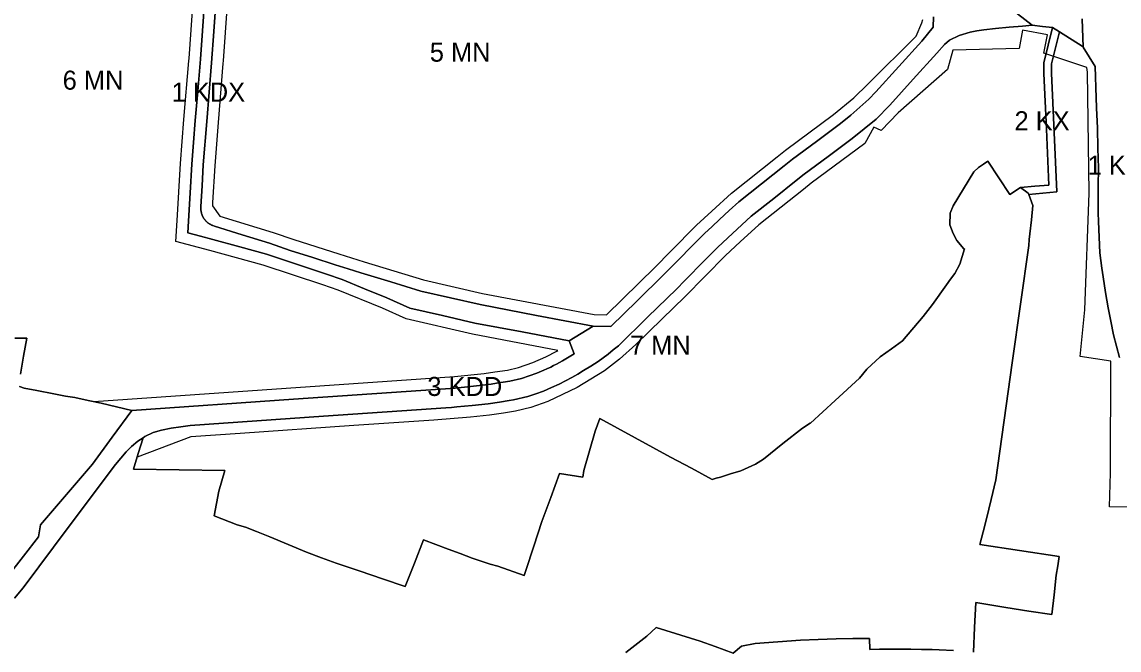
# Model space of a CAD drawing. Extents: x -294445 to -292055, y 21869 to 23693.
# Drawn here: x -294152 to -293575, y 22472 to 22801 of the extents above; entities that cross this region are included whole.
import ezdxf

# ---------------------------------------------------------------- set-up
doc = ezdxf.new("R2010")
doc.units = 0
for name, color, linetype in [('linie_rozgraniczajace', 7, 'Continuous'), ('linie_zabudowy_nieprzekraczalne', 7, 'Continuous'), ('oznaczenia_przeznaczen', 7, 'Continuous')]:
    doc.layers.add(name, color=color, linetype=linetype)

msp = doc.modelspace()

# ---------------------------------------------------------------- linework, layer by layer
at = {"layer": 'linie_rozgraniczajace'}
for points in [[(-294055.939, 22811.926), (-294056.993, 22796.91), (-294058.047, 22781.895), (-294059.436, 22765.133), (-294060.723, 22749.688), (-294061.62, 22738.233), (-294062.516, 22726.779), (-294063.392, 22711.785), (-294064.269, 22696.791), (-294064.663, 22690.759), (-294058.067, 22689.014), (-294051.47, 22687.27), (-294037.37, 22683.355), (-294023.27, 22679.44), (-294007.52, 22674.26), (-293991.77, 22669.08), (-293983.521, 22666.139), (-293971.745, 22661.379), (-293959.97, 22656.62), (-293947.94, 22651.2)], [(-294064.663, 22690.759), (-294064.269, 22696.791), (-294063.392, 22711.785), (-294062.516, 22726.779), (-294061.62, 22738.233), (-294060.723, 22749.688), (-294059.436, 22765.133), (-294058.047, 22781.895), (-294056.993, 22796.91), (-294055.939, 22811.926)], [(-294054.871, 22696.625), (-294055.01, 22696.764), (-294055.147, 22696.905), (-294055.281, 22697.05), (-294055.412, 22697.197), (-294055.54, 22697.346), (-294055.665, 22697.498), (-294055.787, 22697.653), (-294055.905, 22697.81), (-294056.021, 22697.97), (-294056.133, 22698.132), (-294056.241, 22698.296), (-294056.347, 22698.462), (-294056.449, 22698.63), (-294056.547, 22698.801), (-294056.643, 22698.973), (-294056.734, 22699.147), (-294056.822, 22699.323), (-294056.907, 22699.501), (-294056.987, 22699.681), (-294057.065, 22699.862), (-294057.138, 22700.044), (-294057.208, 22700.229), (-294057.274, 22700.414), (-294057.336, 22700.601), (-294057.394, 22700.789), (-294057.449, 22700.978), (-294057.499, 22701.168), (-294057.546, 22701.359), (-294057.589, 22701.551), (-294057.628, 22701.744), (-294057.663, 22701.938), (-294057.694, 22702.132), (-294057.721, 22702.327), (-294057.745, 22702.523), (-294057.764, 22702.719), (-294057.779, 22702.915), (-294057.79, 22703.112), (-294057.798, 22703.308), (-294057.801, 22703.505), (-294057.8, 22703.702), (-294057.795, 22703.899), (-294057.787, 22704.095), (-294057.774, 22704.292), (-294057.757, 22704.488), (-294057.144, 22715.429), (-294056.53, 22726.37), (-294054.742, 22749.204), (-294053.455, 22764.651), (-294052.168, 22780.098), (-294051.011, 22796.447), (-294049.96, 22811.42)], [(-294049.96, 22811.42), (-294051.011, 22796.447)], [(-293632.243, 22808.79), (-293620.646, 22799.786), (-293625.664, 22799.312), (-293632.795, 22798.707), (-293639.941, 22798.101), (-293646.104, 22797.435), (-293649.699, 22796.816), (-293653.294, 22796.197), (-293659.122, 22794.43), (-293664.139, 22791.899), (-293666.793, 22789.583), (-293670.859, 22785.131), (-293683.199, 22771.475), (-293695.538, 22757.82), (-293702.68, 22750.51), (-293708.999, 22745.357), (-293715.319, 22740.204), (-293727.944, 22730.846), (-293740.569, 22721.487), (-293744.698, 22718.136), (-293756.539, 22708.788), (-293768.379, 22699.441), (-293773.297, 22694.898), (-293778.214, 22690.355), (-293786.036, 22683.22), (-293792.729, 22676.434), (-293803.497, 22665.517), (-293807.573, 22661.384)], [(-293594.377, 22803.197), (-293593.872, 22788.256), (-293594.388, 22788.781), (-293606.347, 22796.324), (-293609.914, 22798.578), (-293615.28, 22799.182), (-293620.646, 22799.786), (-293632.243, 22808.79)], [(-294159.072, 22510.604), (-294151.168, 22520.795), (-294143.263, 22530.986), (-294142.717, 22534.173), (-294142.17, 22537.36), (-294128.512, 22553.28), (-294114.854, 22569.199), (-294104.502, 22583.335), (-294094.15, 22597.47), (-294009.075, 22603.335), (-293924, 22609.2), (-293916.062, 22610.027), (-293908.124, 22610.853), (-293905.203, 22611.265), (-293902.282, 22611.677), (-293895.42, 22612.762), (-293889.148, 22614.248), (-293885.152, 22615.6), (-293881.157, 22616.953), (-293877.46, 22618.558), (-293875.901, 22619.235), (-293873.763, 22620.163), (-293872.289, 22620.948), (-293870.724, 22621.781), (-293867.684, 22623.4), (-293861.421, 22627.116), (-293864.117, 22633.958), (-293851.523, 22641.744), (-293842.173, 22641.565), (-293828.4, 22655.019), (-293814.627, 22668.473), (-293810.584, 22672.572), (-293806.541, 22676.671), (-293799.756, 22683.551), (-293792.97, 22690.43), (-293788.985, 22694.065), (-293785, 22697.7), (-293779.94, 22702.375), (-293774.88, 22707.05), (-293762.94, 22716.475), (-293751, 22725.9), (-293746.7, 22729.39), (-293734.08, 22738.745), (-293721.459, 22748.1), (-293715.926, 22752.612), (-293706.589, 22760.92), (-293702.785, 22764.716), (-293690.713, 22778.075), (-293678.641, 22791.434), (-293672.799, 22798.844), (-293672.605, 22804.206)], [(-293672.605, 22804.206), (-293672.799, 22798.844), (-293678.641, 22791.434), (-293690.713, 22778.075), (-293702.785, 22764.716), (-293706.589, 22760.92), (-293715.926, 22752.612), (-293721.459, 22748.1), (-293734.08, 22738.745), (-293746.7, 22729.39), (-293751, 22725.9), (-293762.94, 22716.475), (-293774.88, 22707.05), (-293779.94, 22702.375), (-293785, 22697.7), (-293788.985, 22694.065), (-293792.97, 22690.43), (-293799.756, 22683.551), (-293806.541, 22676.671), (-293810.584, 22672.572), (-293814.627, 22668.473), (-293828.4, 22655.019), (-293842.173, 22641.565), (-293851.523, 22641.744), (-293881.264, 22647.374), (-293911.005, 22653.003), (-293926.61, 22656.574), (-293942.214, 22660.145), (-293957.921, 22664.911), (-293973.627, 22669.677), (-293980.377, 22671.79), (-293987.128, 22673.902), (-293998.959, 22677.711), (-294010.79, 22681.52), (-294021.665, 22685.221), (-294036.129, 22689.701), (-294050.592, 22694.182), (-294051.592, 22694.525), (-294051.759, 22694.591), (-294051.941, 22694.667), (-294052.121, 22694.747), (-294052.299, 22694.83), (-294052.476, 22694.917), (-294052.651, 22695.008), (-294052.824, 22695.102), (-294052.995, 22695.199), (-294053.164, 22695.3), (-294053.331, 22695.404), (-294053.496, 22695.512), (-294053.658, 22695.623), (-294053.818, 22695.737), (-294053.976, 22695.855), (-294054.132, 22695.976), (-294054.285, 22696.099), (-294054.435, 22696.226), (-294054.583, 22696.356), (-294054.728, 22696.489), (-294054.871, 22696.625)], [(-293574.744, 22625.222), (-293577.87, 22637.216), (-293579.304, 22644.235), (-293580.738, 22651.254), (-293582.053, 22659.409), (-293583.368, 22667.564), (-293584.1, 22672.161), (-293584.572, 22676.205), (-293585.045, 22680.249), (-293585.422, 22688.433), (-293585.799, 22696.617), (-293585.885, 22701.145), (-293585.97, 22705.674), (-293585.87, 22715.192), (-293585.77, 22724.711), (-293586.07, 22735.224), (-293586.369, 22745.737), (-293586.761, 22756.424), (-293587.153, 22767.111), (-293587.332, 22772.613), (-293587.511, 22778.115), (-293593.872, 22788.256), (-293594.377, 22803.197)], [(-294093.3, 22566.59), (-294090.744, 22574.851), (-294088.188, 22583.112), (-294087.198, 22583.768), (-294082.911, 22585.833), (-294078.507, 22587.079), (-294073.362, 22588.17), (-294068.385, 22588.878), (-294063.428, 22589.564), (-293993.283, 22594.4), (-293928.929, 22598.836), (-293925.936, 22599.043), (-293923.138, 22599.236), (-293915.113, 22600.071), (-293906.727, 22600.951), (-293900.803, 22601.787), (-293895.655, 22602.601), (-293893.484, 22602.944), (-293885.941, 22604.776), (-293881.748, 22606.195), (-293877.556, 22607.615), (-293873.485, 22609.382), (-293869.415, 22611.149), (-293866.1, 22612.914), (-293862.784, 22614.679), (-293859.659, 22616.53), (-293856.533, 22618.381), (-293852.72, 22620.741), (-293848.906, 22623.101), (-293846.275, 22625.045), (-293843.644, 22626.988), (-293840.949, 22629.202), (-293838.255, 22631.416), (-293822.914, 22646.4), (-293807.573, 22661.384), (-293803.497, 22665.517), (-293792.729, 22676.434), (-293786.036, 22683.22), (-293778.214, 22690.355), (-293773.297, 22694.898), (-293768.379, 22699.441), (-293756.539, 22708.788), (-293744.698, 22718.136), (-293740.569, 22721.487), (-293727.944, 22730.846), (-293715.319, 22740.204), (-293708.999, 22745.357), (-293702.68, 22750.51), (-293695.538, 22757.82), (-293683.199, 22771.475), (-293670.859, 22785.131), (-293666.793, 22789.583), (-293664.139, 22791.899), (-293659.122, 22794.43), (-293653.294, 22796.197), (-293649.699, 22796.816), (-293646.104, 22797.435), (-293639.941, 22798.101), (-293632.795, 22798.707), (-293625.664, 22799.312), (-293620.646, 22799.786), (-293615.28, 22799.182), (-293609.914, 22798.578), (-293612.182, 22789.317), (-293614.45, 22780.055), (-293614.446, 22774.491), (-293613.144, 22745.159), (-293611.842, 22715.826), (-293619.296, 22715.163), (-293626.75, 22714.5), (-293632.33, 22710.92), (-293643.92, 22728.38), (-293646.24, 22726.87), (-293648.85, 22724.99), (-293651.33, 22722.81), (-293656.77, 22713.825), (-293662.21, 22704.84), (-293663.74, 22701.1), (-293664, 22694.98), (-293662.176, 22690.293), (-293660.22, 22686.63), (-293656.52, 22682.35), (-293656.311, 22682.257), (-293658.609, 22674.265), (-293661.389, 22669.401), (-293663.527, 22666.412), (-293665.664, 22663.423), (-293673.145, 22653.11), (-293677.927, 22646.72), (-293688.788, 22633.905), (-293694.705, 22629.763), (-293700.622, 22625.62), (-293707.548, 22619.06), (-293711.492, 22614.359), (-293724.339, 22602.583), (-293737.185, 22590.807), (-293737.352, 22590.702), (-293741.435, 22588.143), (-293751.694, 22579.988), (-293761.952, 22571.833)], [(-294051.011, 22796.447), (-294052.168, 22780.098), (-294053.455, 22764.651), (-294054.742, 22749.204), (-294056.53, 22726.37), (-294057.144, 22715.429), (-294057.757, 22704.488), (-294057.774, 22704.292), (-294057.787, 22704.095), (-294057.795, 22703.899), (-294057.8, 22703.702), (-294057.801, 22703.505), (-294057.798, 22703.308), (-294057.79, 22703.112), (-294057.779, 22702.915), (-294057.764, 22702.719), (-294057.745, 22702.523), (-294057.721, 22702.327), (-294057.694, 22702.132), (-294057.663, 22701.938), (-294057.628, 22701.744), (-294057.589, 22701.551), (-294057.546, 22701.359), (-294057.499, 22701.168), (-294057.449, 22700.978), (-294057.394, 22700.789), (-294057.336, 22700.601), (-294057.274, 22700.414), (-294057.208, 22700.229), (-294057.138, 22700.044), (-294057.065, 22699.862), (-294056.987, 22699.681), (-294056.907, 22699.501), (-294056.822, 22699.323), (-294056.734, 22699.147), (-294056.643, 22698.973), (-294056.547, 22698.801), (-294056.449, 22698.63), (-294056.347, 22698.462), (-294056.241, 22698.296), (-294056.133, 22698.132), (-294056.021, 22697.97), (-294055.905, 22697.81), (-294055.787, 22697.653), (-294055.665, 22697.498), (-294055.54, 22697.346), (-294055.412, 22697.197), (-294055.281, 22697.05), (-294055.147, 22696.905), (-294055.01, 22696.764), (-294054.871, 22696.625), (-294054.728, 22696.489), (-294054.583, 22696.356), (-294054.435, 22696.226), (-294054.285, 22696.099), (-294054.132, 22695.976), (-294053.976, 22695.855), (-294053.818, 22695.737), (-294053.658, 22695.623), (-294053.496, 22695.512), (-294053.331, 22695.404), (-294053.164, 22695.3), (-294052.995, 22695.199), (-294052.824, 22695.102), (-294052.651, 22695.008), (-294052.476, 22694.917), (-294052.299, 22694.83), (-294052.121, 22694.747), (-294051.941, 22694.667), (-294051.759, 22694.591), (-294051.592, 22694.525), (-294050.592, 22694.182), (-294036.129, 22689.701), (-294021.665, 22685.221), (-294010.79, 22681.52), (-293998.959, 22677.711), (-293987.128, 22673.902), (-293980.377, 22671.79), (-293973.627, 22669.677), (-293957.921, 22664.911), (-293942.214, 22660.145), (-293926.61, 22656.574), (-293911.005, 22653.003), (-293881.264, 22647.374), (-293851.523, 22641.744), (-293864.117, 22633.958), (-293888.894, 22638.644), (-293913.67, 22643.33), (-293930.805, 22647.265), (-293947.94, 22651.2), (-293959.97, 22656.62), (-293971.745, 22661.379), (-293983.521, 22666.139), (-293991.77, 22669.08), (-294007.52, 22674.26), (-294023.27, 22679.44), (-294037.37, 22683.355), (-294051.47, 22687.27), (-294058.067, 22689.014), (-294064.663, 22690.759)], [(-293651.55, 22470.39), (-293650.913, 22483.44), (-293650.275, 22496.49), (-293634.42, 22493.81), (-293622.365, 22492.02), (-293610.31, 22490.23), (-293609.155, 22500.545), (-293608, 22510.86), (-293607.24, 22515.735), (-293606.48, 22520.61), (-293627.355, 22523.785), (-293648.23, 22526.96), (-293646.45, 22533.68), (-293644.67, 22540.4), (-293642.232, 22550.672), (-293639.793, 22560.943), (-293631.132, 22622.502), (-293622.47, 22684.06), (-293622.151, 22687.132), (-293621.831, 22690.203), (-293621.061, 22697.602), (-293620.29, 22705), (-293622.495, 22710.863), (-293615.086, 22711.521), (-293607.676, 22712.18), (-293609.061, 22743.381), (-293610.446, 22774.581), (-293610.45, 22779.574), (-293608.399, 22787.949), (-293606.347, 22796.324), (-293594.388, 22788.781), (-293593.872, 22788.256), (-293587.511, 22778.115), (-293587.332, 22772.613), (-293587.153, 22767.111), (-293586.761, 22756.424), (-293586.369, 22745.737), (-293586.07, 22735.224), (-293585.77, 22724.711), (-293585.87, 22715.192), (-293585.97, 22705.674), (-293585.885, 22701.145), (-293585.799, 22696.617), (-293585.422, 22688.433), (-293585.045, 22680.249), (-293584.572, 22676.205), (-293584.1, 22672.161), (-293583.368, 22667.564), (-293582.053, 22659.409), (-293580.738, 22651.254), (-293579.304, 22644.235), (-293577.87, 22637.216), (-293574.744, 22625.222)], [(-294155.766, 22498.821), (-294151.315, 22504.293), (-294126.983, 22536.659), (-294102.652, 22569.025), (-294099.867, 22572.362), (-294097.082, 22575.7), (-294094.292, 22578.469), (-294090.901, 22581.313), (-294088.188, 22583.112), (-294090.744, 22574.851), (-294093.3, 22566.59), (-294069.245, 22566.24), (-294045.19, 22565.89), (-294048.36, 22555.07), (-294049.625, 22548.57), (-294050.89, 22542.07), (-294038.69, 22537.28), (-294034.42, 22536.08), (-294028.53, 22533.775), (-294021.47, 22531.04), (-294011.875, 22526.99), (-294002.28, 22522.94), (-293994.435, 22520.02), (-293986.59, 22517.1), (-293980.35, 22515.085), (-293974.11, 22513.07), (-293962.221, 22509.035), (-293950.332, 22504.999), (-293945.522, 22517.263), (-293940.713, 22529.527), (-293934.276, 22527.074), (-293927.84, 22524.62), (-293921.485, 22522.235), (-293915.13, 22519.85), (-293905.71, 22516.63), (-293901.69, 22515.61), (-293887.83, 22510.69), (-293886.963, 22513.326), (-293882.737, 22526.178), (-293878.51, 22539.03), (-293873.845, 22551.685), (-293869.18, 22564.34), (-293856.985, 22562.445), (-293856.44, 22565.93), (-293853.412, 22576.217), (-293850.385, 22586.503), (-293848.05, 22593.16), (-293829.44, 22583.026), (-293810.83, 22572.893), (-293799.848, 22567.042), (-293788.865, 22561.191), (-293786.752, 22561.765), (-293784.638, 22562.338), (-293779.234, 22564.032), (-293773.83, 22565.725), (-293766.175, 22569.251), (-293761.952, 22571.833), (-293751.694, 22579.988), (-293741.435, 22588.143), (-293737.352, 22590.702), (-293737.185, 22590.807), (-293724.339, 22602.583), (-293711.492, 22614.359), (-293707.548, 22619.06), (-293700.622, 22625.62), (-293694.705, 22629.763), (-293688.788, 22633.905), (-293677.927, 22646.72), (-293673.145, 22653.11), (-293665.664, 22663.423), (-293663.527, 22666.412), (-293661.389, 22669.401), (-293658.609, 22674.265), (-293656.311, 22682.257), (-293656.52, 22682.35), (-293660.22, 22686.63), (-293662.176, 22690.293), (-293664, 22694.98), (-293663.74, 22701.1), (-293662.21, 22704.84), (-293656.77, 22713.825), (-293651.33, 22722.81), (-293648.85, 22724.99), (-293646.24, 22726.87), (-293643.92, 22728.38), (-293632.33, 22710.92), (-293626.75, 22714.5), (-293622.75, 22711.54), (-293622.495, 22710.863), (-293620.29, 22705)], [(-293620.29, 22705), (-293621.061, 22697.602), (-293621.831, 22690.203), (-293622.151, 22687.132), (-293622.47, 22684.06), (-293631.132, 22622.502), (-293639.793, 22560.943), (-293642.232, 22550.672), (-293644.67, 22540.4), (-293646.45, 22533.68), (-293648.23, 22526.96), (-293627.355, 22523.785), (-293606.48, 22520.61), (-293607.24, 22515.735), (-293608, 22510.86), (-293609.155, 22500.545), (-293610.31, 22490.23), (-293622.365, 22492.02), (-293634.42, 22493.81), (-293650.275, 22496.49), (-293650.913, 22483.44), (-293651.55, 22470.39)], [(-293807.573, 22661.384), (-293822.914, 22646.4), (-293838.255, 22631.416), (-293840.949, 22629.202), (-293843.644, 22626.988), (-293846.275, 22625.045), (-293848.906, 22623.101), (-293852.72, 22620.741), (-293856.533, 22618.381), (-293859.659, 22616.53), (-293862.784, 22614.679), (-293866.1, 22612.914), (-293869.415, 22611.149), (-293873.485, 22609.382), (-293877.556, 22607.615), (-293881.748, 22606.195), (-293885.941, 22604.776), (-293893.484, 22602.944), (-293895.655, 22602.601), (-293900.803, 22601.787), (-293906.727, 22600.951), (-293915.113, 22600.071), (-293923.138, 22599.236), (-293925.936, 22599.043), (-293928.929, 22598.836), (-293993.283, 22594.4), (-294063.428, 22589.564), (-294068.385, 22588.878), (-294073.362, 22588.17), (-294078.507, 22587.079), (-294082.911, 22585.833), (-294087.198, 22583.768), (-294088.188, 22583.112), (-294090.901, 22581.313), (-294094.292, 22578.469), (-294097.082, 22575.7), (-294099.867, 22572.362), (-294102.652, 22569.025), (-294126.983, 22536.659), (-294151.315, 22504.293), (-294155.766, 22498.821)], [(-293947.94, 22651.2), (-293930.805, 22647.265), (-293913.67, 22643.33), (-293888.894, 22638.644), (-293864.117, 22633.958), (-293861.421, 22627.116), (-293867.684, 22623.4), (-293870.724, 22621.781), (-293872.289, 22620.948), (-293873.763, 22620.163), (-293875.901, 22619.235), (-293877.46, 22618.558), (-293881.157, 22616.953), (-293885.152, 22615.6), (-293889.148, 22614.248), (-293895.42, 22612.762), (-293902.282, 22611.677), (-293905.203, 22611.265), (-293908.124, 22610.853), (-293916.062, 22610.027), (-293924, 22609.2), (-294009.075, 22603.335), (-294094.15, 22597.47), (-294102.23, 22599.395), (-294110.31, 22601.32), (-294117.16, 22602.725), (-294124.01, 22604.13), (-294129.08, 22604.96), (-294135.175, 22606.1), (-294144.115, 22607.845), (-294150.72, 22609.19), (-294153.17, 22609.97)], [(-294152.71, 22616.49), (-294151.02, 22625.965), (-294149.33, 22635.44), (-294155.605, 22635.36)], [(-294155.605, 22635.36), (-294149.33, 22635.44), (-294151.02, 22625.965), (-294152.71, 22616.49)], [(-294153.17, 22609.97), (-294150.72, 22609.19), (-294144.115, 22607.845), (-294135.175, 22606.1), (-294129.08, 22604.96), (-294124.01, 22604.13), (-294117.16, 22602.725), (-294110.31, 22601.32), (-294102.23, 22599.395), (-294094.15, 22597.47), (-294104.502, 22583.335), (-294114.854, 22569.199), (-294128.512, 22553.28), (-294142.17, 22537.36), (-294142.717, 22534.173), (-294143.263, 22530.986), (-294151.168, 22520.795), (-294159.072, 22510.604)], [(-293761.952, 22571.833), (-293766.175, 22569.251), (-293773.83, 22565.725), (-293779.234, 22564.032), (-293784.638, 22562.338), (-293786.752, 22561.765), (-293788.865, 22561.191), (-293799.848, 22567.042), (-293810.83, 22572.893), (-293829.44, 22583.026), (-293848.05, 22593.16), (-293850.385, 22586.503), (-293853.412, 22576.217), (-293856.44, 22565.93), (-293856.985, 22562.445), (-293869.18, 22564.34), (-293873.845, 22551.685), (-293878.51, 22539.03), (-293882.737, 22526.178), (-293886.963, 22513.326), (-293887.83, 22510.69), (-293901.69, 22515.61), (-293905.71, 22516.63), (-293915.13, 22519.85), (-293921.485, 22522.235), (-293927.84, 22524.62), (-293934.276, 22527.074), (-293940.713, 22529.527), (-293945.522, 22517.263), (-293950.332, 22504.999), (-293962.221, 22509.035), (-293974.11, 22513.07), (-293980.35, 22515.085), (-293986.59, 22517.1), (-293994.435, 22520.02), (-294002.28, 22522.94), (-294011.875, 22526.99), (-294021.47, 22531.04), (-294028.53, 22533.775), (-294034.42, 22536.08), (-294038.69, 22537.28), (-294050.89, 22542.07), (-294049.625, 22548.57), (-294048.36, 22555.07), (-294045.19, 22565.89), (-294069.245, 22566.24), (-294093.3, 22566.59)], [(-293834.33, 22470.28), (-293823.35, 22478.86), (-293818.38, 22483.44), (-293795.33, 22476.2), (-293787.308, 22473.333), (-293777.927, 22469.988), (-293773.45, 22473.55), (-293766.38, 22474.9), (-293754.42, 22475.775), (-293742.46, 22476.65), (-293733.135, 22477.06), (-293723.81, 22477.47), (-293714.98, 22477.57), (-293706.15, 22477.67), (-293706.06, 22471.91), (-293700.9, 22471.99), (-293695.74, 22472.07), (-293690.108, 22472), (-293684.475, 22471.93), (-293678.843, 22471.86), (-293673.21, 22471.79), (-293669.485, 22471.61), (-293662.035, 22471.25)], [(-293662.035, 22471.25), (-293669.485, 22471.61), (-293673.21, 22471.79), (-293678.843, 22471.86), (-293684.475, 22471.93), (-293690.108, 22472), (-293695.74, 22472.07), (-293700.9, 22471.99), (-293706.06, 22471.91), (-293706.15, 22477.67), (-293714.98, 22477.57), (-293723.81, 22477.47), (-293733.135, 22477.06), (-293742.46, 22476.65), (-293754.42, 22475.775), (-293766.38, 22474.9), (-293773.45, 22473.55), (-293777.927, 22469.988), (-293787.308, 22473.333), (-293795.33, 22476.2), (-293818.38, 22483.44), (-293823.35, 22478.86), (-293834.33, 22470.28)]]:
    msp.add_lwpolyline(points, dxfattribs=at)
msp.add_lwpolyline([(-293626.75, 22714.5), (-293619.296, 22715.163), (-293611.842, 22715.826), (-293613.144, 22745.159), (-293614.446, 22774.491), (-293614.45, 22780.055), (-293612.182, 22789.317), (-293609.914, 22798.578), (-293606.347, 22796.324), (-293608.399, 22787.949), (-293610.45, 22779.574), (-293610.446, 22774.581), (-293609.061, 22743.381), (-293607.676, 22712.18), (-293615.086, 22711.521), (-293622.495, 22710.863), (-293622.75, 22711.54)], close=True, dxfattribs=at)
at = {"layer": 'linie_zabudowy_nieprzekraczalne'}
for points in [[(-294114.142, 22602.106), (-293924.517, 22615.179), (-293908.854, 22616.809), (-293903.17, 22617.612), (-293896.581, 22618.653), (-293890.805, 22620.021), (-293883.317, 22622.556), (-293876.372, 22625.572), (-293870.624, 22628.632), (-293870.048, 22628.973), (-293914.899, 22637.456), (-293949.862, 22645.485), (-293962.327, 22651.101), (-293985.653, 22660.529), (-293993.715, 22663.404), (-294025.011, 22673.696), (-294053.04, 22681.479), (-294070.973, 22686.221), (-294070.257, 22697.162), (-294068.503, 22727.188), (-294066.704, 22750.171), (-294064.13, 22781.059), (-294064.031, 22782.337), (-294061.919, 22812.431)], [(-294043.981, 22810.914), (-294046.078, 22781.033), (-294046.188, 22779.618), (-294048.762, 22748.721), (-294050.544, 22725.963), (-294051.637, 22706.635), (-294051.778, 22704.942), (-294047.875, 22699.551), (-294019.817, 22690.93), (-294008.904, 22687.216), (-293985.313, 22679.621), (-293971.86, 22675.411), (-293940.672, 22665.948), (-293909.777, 22658.877), (-293850.903, 22647.733), (-293844.57, 22647.612), (-293818.86, 22672.726), (-293810.813, 22680.884), (-293797.131, 22694.756), (-293789.058, 22702.12), (-293778.78, 22711.615), (-293754.749, 22730.584), (-293750.379, 22734.132), (-293725.144, 22752.838), (-293714.419, 22761.583), (-293707.133, 22768.854), (-293681.609, 22794.116), (-293678.724, 22801.02), (-293678.121, 22802.854)], [(-293555.782, 22546.61), (-293579.925, 22546.851), (-293579.442, 22564.721), (-293579.207, 22623.228), (-293595.417, 22625.699), (-293593, 22650.331), (-293590.644, 22711.589), (-293590.644, 22711.589), (-293590.644, 22711.589), (-293590.644, 22711.589), (-293590.644, 22711.589), (-293591.599, 22775.113), (-293591.599, 22775.113), (-293591.599, 22775.113), (-293591.599, 22775.113), (-293591.599, 22775.113), (-293591.955, 22777.626), (-293614.503, 22785.159), (-293612.627, 22794.649), (-293625.712, 22797.147), (-293627.512, 22787.627), (-293662.301, 22786.622), (-293665.116, 22776.576), (-293691.165, 22753.711), (-293700.144, 22744.455), (-293703.954, 22746.291), (-293708.7, 22737.642)], [(-293708.7, 22737.642), (-293736.89, 22716.746), (-293740.949, 22713.451), (-293764.479, 22694.876), (-293774.156, 22685.935), (-293781.875, 22678.894), (-293803.34, 22657.131), (-293815.227, 22645.521), (-293829.043, 22632.027), (-293837.645, 22624.28), (-293845.492, 22618.155), (-293859.926, 22609.395), (-293875.291, 22602.047), (-293884.267, 22599.008), (-293892.306, 22597.055), (-293898.6, 22596.061), (-293905.986, 22594.996), (-293916.062, 22593.94), (-293935.224, 22592.388), (-293977.378, 22589.482), (-294037.142, 22585.294), (-294063.032, 22583.577), (-294063.032, 22583.577), (-294063.032, 22583.577), (-294063.032, 22583.577), (-294063.032, 22583.577), (-294091.331, 22572.955), (-294091.331, 22572.955), (-294091.331, 22572.955), (-294091.331, 22572.955)]]:
    msp.add_lwpolyline(points, dxfattribs=at)

# ---------------------------------------------------------------- texts
at = {"layer": 'oznaczenia_przeznaczen'}
for s, p in [('5 MN', (-293937.42, 22780.641)), ('6 MN', (-294130.494, 22765.923)), ('1 KDX', (-294073.19, 22759.651)), ('2 KX', (-293629.939, 22744.59)), ('1 KDZ', (-293591.501, 22721.259)), ('7 MN', (-293832.181, 22626.701)), ('3 KDD', (-293938.713, 22605.027))]:
    msp.add_text(s, height=10, dxfattribs=at).set_placement(p)

doc.saveas('drawing.dxf')
